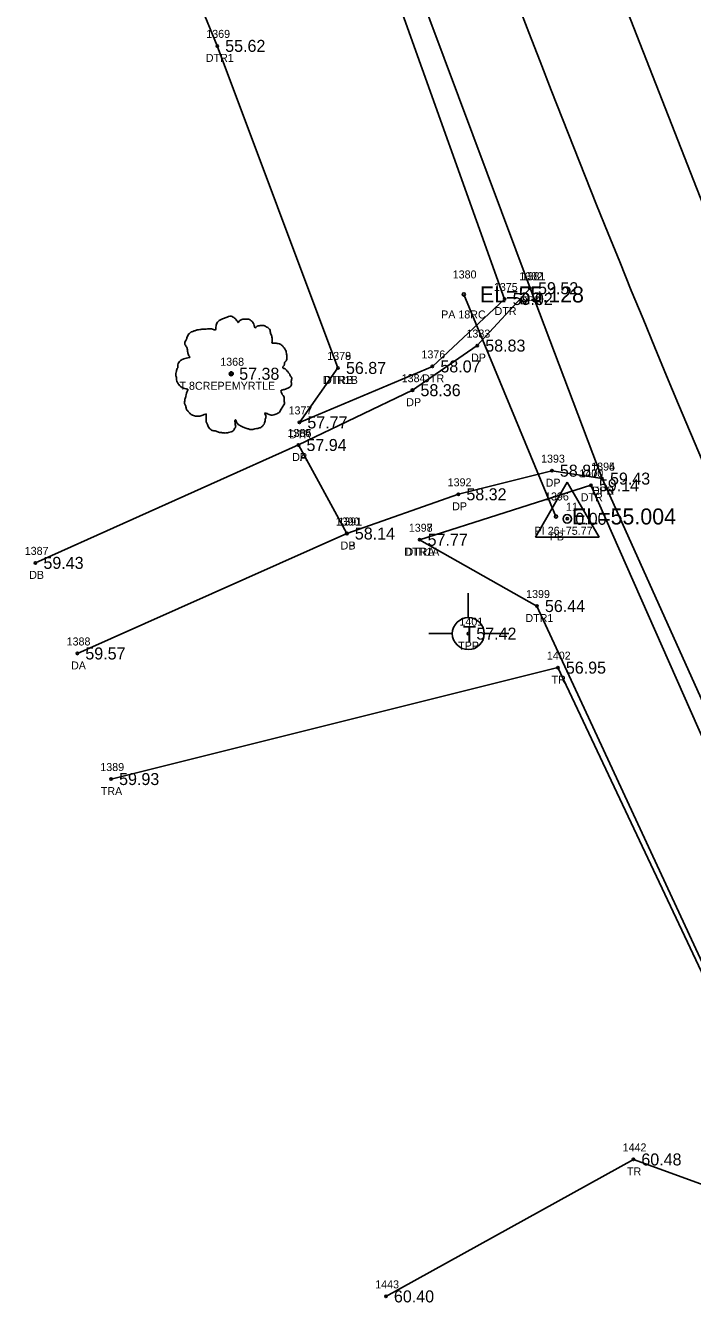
# Model space of a CAD drawing. Extents: x 2396531 to 2397633, y 770203 to 772837.
# Drawn here: x 2397059.6 to 2397143, y 771006.4 to 771166.1 of the extents above; entities that cross this region are included whole.
import ezdxf

# ---------------------------------------------------------------- set-up
doc = ezdxf.new("R2010")
doc.units = 0
for name, color, linetype in [('RD_EX_DR_Pipe', 7, 'Continuous'), ('RD_EX_DR_Pipe_txCode', 7, 'Continuous'), ('RD_EX_Driveway', 7, 'Continuous'), ('RD_EX_Driveway_txCode', 7, 'Continuous'), ('RD_EX_H2O', 7, 'Continuous'), ('RD_EX_H2O_txCode', 7, 'Continuous'), ('RD_EX_Road', 7, 'Continuous'), ('RD_EX_Road_txCode', 7, 'Continuous'), ('RD_EX_TX_Driveway_ELEV', 7, 'Continuous'), ('RD_EX_TX_H2O_ELEV', 7, 'Continuous'), ('RD_EX_TX_Road_ELEV', 7, 'Continuous'), ('RD_EX_TX_UT_ELEV', 7, 'Continuous'), ('RD_EX_TX_VEG_ELEV', 7, 'Continuous'), ('RD_EX_UT', 7, 'Continuous'), ('RD_EX_UT_txCode', 7, 'Continuous'), ('RD_EX_VEG', 7, 'Continuous'), ('RD_EX_VEG_txCode', 7, 'Continuous'), ('RD_HC_Cl', 7, 'Continuous'), ('RD_HC_Data', 7, 'Continuous'), ('RD_HC_Survey_ELEV', 7, 'Continuous'), ('RD_HC_txCode', 7, 'Continuous'), ('RD_SMD_Locator', 7, 'Continuous'), ('RD_TX_Pipe_ElevEX', 7, 'Continuous')]:
    doc.layers.add(name, color=color, linetype=linetype)

msp = doc.modelspace()

# ---------------------------------------------------------------- linework, layer by layer
at = {"layer": 'RD_EX_DR_Pipe'}
msp.add_line((2397114.38, 771132.51), (2397125.9, 771104.77), dxfattribs=at)
at = {"layer": 'RD_EX_Driveway'}
for p, q in [((2397093.7, 771113.7), (2397060.81, 771098.97)), ((2397066.05, 771087.65), (2397099.75, 771102.64))]:
    msp.add_line(p, q, dxfattribs=at)
msp.add_lwpolyline([(2397122.66, 771133.29), (2397116.06, 771126.12), (2397107.96, 771120.55), (2397093.7, 771113.7), (2397099.75, 771102.64), (2397113.7, 771107.54), (2397125.39, 771110.49), (2397131.66, 771109.5)], dxfattribs=at)
at = {"layer": 'RD_EX_H2O'}
for points in [[(2397089.23, 771210.58), (2397074.63, 771209.23), (2397066.11, 771205.28), (2397068.66, 771199.78), (2397083.54, 771163.57), (2397098.64, 771123.33)], [(2397089.23, 771210.58), (2397105.65, 771170.55), (2397119.48, 771131.94), (2397110.45, 771123.52), (2397093.81, 771116.52), (2397098.64, 771123.33)], [(2397108.85, 771101.86), (2397130.27, 771108.67), (2397157.99, 771046.03), (2397184.53, 770991.63), (2397224.53, 770918.86), (2397257.48, 770863.23)], [(2397108.85, 771101.86), (2397123.52, 771093.58), (2397147.97, 771040.86), (2397177.5, 770986.79), (2397217.86, 770915.5), (2397251.15, 770859.33)]]:
    msp.add_lwpolyline(points, dxfattribs=at)
at = {"layer": 'RD_EX_Road'}
for points in [[(2397113.76, 771228.75), (2397130.87, 771177.98), (2397154.19, 771118.49), (2397170.38, 771081.25), (2397178.53, 771063.49), (2397207.96, 771004.56), (2397238.54, 770949.11), (2397245.72, 770936.59), (2397280.76, 770876.73)], [(2397093.16, 771212.62), (2397108.35, 771171.65), (2397122.66, 771133.29), (2397131.66, 771109.5), (2397159.86, 771046.96), (2397187.02, 770992.86), (2397227.29, 770920.43), (2397260.16, 770864.73)]]:
    msp.add_lwpolyline(points, dxfattribs=at)
at = {"layer": 'RD_EX_UT'}
for p, q in [((2397114.94, 771095.2), (2397114.94, 771092.13)), ((2397110.01, 771090.15), (2397112.94, 771090.15)), ((2397116.94, 771090.15), (2397120.01, 771090.15))]:
    msp.add_line(p, q, dxfattribs=at)
msp.add_circle((2397114.94, 771090.13), 2, dxfattribs=at)
at = {"layer": 'RD_EX_VEG'}
msp.add_lwpolyline([(2397070.27, 771071.96), (2397126.14, 771085.88), (2397159.22, 771015.86), (2397135.58, 771024.43), (2397104.64, 771007.32)], dxfattribs=at)
for centre, radius in [((2397085.29, 771122.6), 0.25), ((2397085.28, 771122.58), 0.0001)]:
    msp.add_circle(centre, radius, dxfattribs=at)
for points in [[(2397085.42, 771129.77), (2397085.12, 771129.79), (2397084.8, 771129.69), (2397084.55, 771129.59), (2397084.32, 771129.52), (2397084.1, 771129.42), (2397083.8, 771129.24), (2397083.57, 771129.04), (2397083.45, 771128.79), (2397083.4, 771128.57), (2397083.35, 771128.3), (2397083.35, 771128.12), (2397083.22, 771128.1), (2397083.07, 771128.12), (2397082.82, 771128.2), (2397082.57, 771128.2), (2397082.32, 771128.2), (2397081.97, 771128.17), (2397081.63, 771128.17), (2397081.35, 771128.12), (2397081.03, 771128.07), (2397080.65, 771127.95), (2397080.3, 771127.82), (2397080, 771127.57), (2397079.75, 771127.1), (2397079.63, 771126.75), (2397079.48, 771126.5), (2397079.63, 771126.05), (2397079.8, 771125.7), (2397079.83, 771125.5), (2397079.9, 771125.07), (2397080, 771124.85), (2397080.13, 771124.65), (2397080.05, 771124.62), (2397079.68, 771124.57), (2397079.38, 771124.47), (2397078.95, 771124.25), (2397078.73, 771124.02), (2397078.63, 771123.7), (2397078.6, 771123.35), (2397078.5, 771123.15), (2397078.43, 771122.87), (2397078.4, 771122.8), (2397078.35, 771122.47), (2397078.45, 771122.02), (2397078.48, 771121.67), (2397078.6, 771121.45), (2397078.75, 771121.27), (2397078.93, 771121.02), (2397079.33, 771120.8), (2397079.65, 771120.7), (2397079.85, 771120.67), (2397079.68, 771120.17), (2397079.63, 771119.82), (2397079.5, 771119.42), (2397079.5, 771119.35), (2397079.45, 771118.87), (2397079.6, 771118.55), (2397079.68, 771118.17), (2397079.85, 771117.95), (2397080.13, 771117.65), (2397080.45, 771117.42), (2397080.95, 771117.3), (2397081.35, 771117.32), (2397081.92, 771117.5), (2397082.17, 771117.57), (2397082.15, 771117.4), (2397082.17, 771117.02), (2397082.17, 771116.6), (2397082.32, 771116.28), (2397082.42, 771116), (2397082.57, 771115.75), (2397082.9, 771115.53), (2397083.3, 771115.45), (2397083.72, 771115.3), (2397084.17, 771115.23), (2397084.67, 771115.2), (2397085.27, 771115.35), (2397085.55, 771115.48), (2397085.65, 771115.65), (2397085.85, 771116.03), (2397085.8, 771116.25), (2397085.82, 771116.85), (2397085.92, 771116.68), (2397086.1, 771116.33), (2397086.6, 771116.03), (2397087, 771115.85), (2397087.47, 771115.7), (2397087.77, 771115.63), (2397088.25, 771115.7), (2397088.62, 771115.78), (2397089, 771115.9), (2397089.3, 771116.18), (2397089.47, 771116.45), (2397089.52, 771116.73), (2397089.6, 771117.1), (2397089.65, 771117.27)], [(2397089.65, 771117.27), (2397089.57, 771117.45), (2397089.52, 771117.7), (2397089.6, 771117.67), (2397089.77, 771117.62), (2397090.05, 771117.5), (2397090.27, 771117.42), (2397090.6, 771117.45), (2397090.87, 771117.55), (2397091.32, 771117.82), (2397091.6, 771118.3), (2397091.87, 771118.7), (2397091.95, 771119.02), (2397091.9, 771119.25), (2397091.87, 771119.75), (2397091.67, 771120), (2397091.62, 771120.12), (2397091.52, 771120.52), (2397091.6, 771120.57), (2397091.87, 771120.62), (2397092.25, 771120.75), (2397092.52, 771120.87), (2397092.75, 771121.05), (2397092.82, 771121.27), (2397092.8, 771121.67), (2397092.85, 771122.07), (2397092.77, 771122.22), (2397092.67, 771122.37), (2397092.6, 771122.57), (2397092.45, 771122.72), (2397092.35, 771122.87), (2397092.25, 771122.97), (2397092.12, 771123.12), (2397091.95, 771123.25), (2397091.8, 771123.3), (2397091.75, 771123.45), (2397091.9, 771123.65), (2397091.95, 771123.75), (2397091.97, 771123.97), (2397092.2, 771124.32), (2397092.25, 771124.72), (2397092.2, 771125.15), (2397092.15, 771125.42), (2397092, 771125.7), (2397091.8, 771125.95), (2397091.67, 771126.12), (2397091.5, 771126.25), (2397091.17, 771126.37), (2397090.92, 771126.42), (2397090.57, 771126.42), (2397090.37, 771126.47), (2397090.4, 771126.52), (2397090.4, 771126.67), (2397090.4, 771126.95), (2397090.32, 771127.4), (2397090.17, 771127.9), (2397090.17, 771127.92), (2397090.07, 771128.17), (2397089.85, 771128.37), (2397089.67, 771128.47), (2397089.47, 771128.59), (2397089.22, 771128.62), (2397088.92, 771128.62), (2397088.65, 771128.57), (2397088.45, 771128.47), (2397088.27, 771128.34), (2397088.2, 771128.49), (2397088.1, 771128.79), (2397088.05, 771128.94), (2397087.9, 771129.12), (2397087.67, 771129.32), (2397087.22, 771129.44), (2397086.6, 771129.37), (2397086.3, 771129.17), (2397086.15, 771128.99), (2397086.1, 771129.12), (2397085.9, 771129.32), (2397085.8, 771129.49), (2397085.62, 771129.62), (2397085.47, 771129.72), (2397085.37, 771129.77)]]:
    msp.add_spline(points, degree=3, dxfattribs=at)
at = {"layer": 'RD_HC_Cl'}
msp.add_arc((2398682.18, 771766.08), 1671.39, 194.59125, 211.50817, dxfattribs=at)
at = {"layer": 'RD_HC_Data'}
for p, q in [((2397123.35, 771102.19), (2397127.32, 771109.07)), ((2397127.32, 771109.07), (2397131.29, 771102.19)), ((2397123.35, 771102.19), (2397131.29, 771102.19))]:
    msp.add_line(p, q, dxfattribs=at)
msp.add_circle((2397127.32, 771104.48), 0.529, dxfattribs=at)
at = {"layer": 'RD_SMD_Locator'}
for centre, radius in [((2397083.54, 771163.57), 0.15), ((2397122.66, 771133.29), 0.15), ((2397122.66, 771133.29), 0.15), ((2397114.38, 771132.51), 0.2), ((2397119.48, 771131.94), 0.15), ((2397116.06, 771126.12), 0.15), ((2397085.29, 771122.6), 0.15), ((2397098.64, 771123.33), 0.15), ((2397098.64, 771123.33), 0.15), ((2397110.45, 771123.52), 0.15), ((2397107.96, 771120.55), 0.15), ((2397093.81, 771116.52), 0.15), ((2397093.7, 771113.7), 0.15), ((2397093.7, 771113.7), 0.15), ((2397125.39, 771110.49), 0.15), ((2397131.66, 771109.5), 0.15), ((2397131.66, 771109.5), 0.15), ((2397130.27, 771108.67), 0.15), ((2397113.7, 771107.54), 0.15), ((2397125.9, 771104.77), 0.2), ((2397127.32, 771104.48), 0.15), ((2397099.75, 771102.64), 0.15), ((2397099.75, 771102.64), 0.15), ((2397108.85, 771101.86), 0.15), ((2397108.85, 771101.86), 0.15), ((2397060.81, 771098.97), 0.15), ((2397123.52, 771093.58), 0.15), ((2397114.94, 771090.13), 0.15), ((2397066.05, 771087.65), 0.15), ((2397126.14, 771085.88), 0.15), ((2397070.27, 771071.96), 0.15), ((2397135.58, 771024.43), 0.15), ((2397104.64, 771007.32), 0.15)]:
    msp.add_circle(centre, radius, dxfattribs=at)

# ---------------------------------------------------------------- texts
at = {"layer": 'RD_EX_DR_Pipe_txCode'}
for s, p in [('1380', (2397112.99, 771134.51)), ('PA 18RC', (2397111.54, 771129.51)), ('1396', (2397124.53, 771106.77)), ('PB', (2397125.12, 771101.77))]:
    msp.add_text(s, height=1, dxfattribs=at).set_placement(p)
at = {"layer": 'RD_EX_Driveway_txCode'}
for s, p in [('1382', (2397121.31, 771134.29)), ('DPA', (2397121.39, 771131.29)), ('1383', (2397114.71, 771127.12)), ('DP', (2397115.28, 771124.12)), ('1384', (2397106.61, 771121.55)), ('DP', (2397107.18, 771118.55)), ('1386', (2397092.33, 771114.7)), ('1385', (2397092.36, 771114.7)), ('DA', (2397092.91, 771111.7)), ('DP', (2397092.92, 771111.7)), ('1393', (2397124.04, 771111.49)), ('1394', (2397130.31, 771110.5)), ('1392', (2397112.36, 771108.54)), ('DP', (2397124.61, 771108.49)), ('DPB', (2397130.4, 771107.5)), ('DP', (2397112.92, 771105.54)), ('1390', (2397098.36, 771103.64)), ('1391', (2397098.68, 771103.64)), ('DB', (2397098.97, 771100.64)), ('DP', (2397098.97, 771100.64)), ('1387', (2397059.47, 771099.97)), ('DB', (2397060.03, 771096.97)), ('1388', (2397064.71, 771088.65)), ('DA', (2397065.26, 771085.65))]:
    msp.add_text(s, height=1, dxfattribs=at).set_placement(p)
at = {"layer": 'RD_EX_H2O_txCode'}
for s, p in [('1369', (2397082.17, 771164.57)), ('DTR1', (2397082.11, 771161.57)), ('1375', (2397118.14, 771132.94)), ('DTR', (2397118.22, 771129.94)), ('1376', (2397109.08, 771124.52)), ('1378', (2397097.3, 771124.33)), ('1379', (2397097.3, 771124.33)), ('DTR1B', (2397096.74, 771121.33)), ('DTRB', (2397096.9, 771121.33)), ('DTR', (2397109.18, 771121.52)), ('1377', (2397092.46, 771117.52)), ('DTR', (2397092.54, 771114.52)), ('1400', (2397128.84, 771109.67)), ('DTR', (2397129, 771106.67)), ('1397', (2397107.5, 771102.86)), ('1398', (2397107.5, 771102.86)), ('DTR1A', (2397106.93, 771099.86)), ('DTRA', (2397107.09, 771099.86)), ('1399', (2397122.17, 771094.58)), ('DTR1', (2397122.08, 771091.58))]:
    msp.add_text(s, height=1, dxfattribs=at).set_placement(p)
at = {"layer": 'RD_EX_Road_txCode'}
for s, p in [('1381', (2397121.6, 771134.29)), ('EPR', (2397121.43, 771131.29)), ('1395', (2397130.31, 771110.5)), ('EPR', (2397130.43, 771107.5))]:
    msp.add_text(s, height=1, dxfattribs=at).set_placement(p)
at = {"layer": 'RD_EX_TX_Driveway_ELEV'}
for s, p in [('59.52', (2397123.66, 771132.54)), ('58.83', (2397117.06, 771125.37)), ('58.36', (2397108.96, 771119.8)), ('57.94', (2397094.7, 771112.95)), ('57.94', (2397094.7, 771112.95)), ('58.87', (2397126.39, 771109.74)), ('59.43', (2397132.66, 771108.75)), ('58.32', (2397114.7, 771106.79)), ('58.14', (2397100.75, 771101.89)), ('58.14', (2397100.75, 771101.89)), ('59.43', (2397061.81, 771098.22)), ('59.57', (2397067.05, 771086.9))]:
    msp.add_text(s, height=1.5, dxfattribs=at).set_placement(p)
at = {"layer": 'RD_EX_TX_H2O_ELEV'}
for s, p in [('55.62', (2397084.54, 771162.82)), ('59.02', (2397120.48, 771131.19)), ('56.87', (2397099.64, 771122.58)), ('56.87', (2397099.64, 771122.58)), ('58.07', (2397111.45, 771122.77)), ('57.77', (2397094.81, 771115.77)), ('59.14', (2397131.27, 771107.92)), ('57.77', (2397109.85, 771101.11)), ('57.77', (2397109.85, 771101.11)), ('56.44', (2397124.52, 771092.83))]:
    msp.add_text(s, height=1.5, dxfattribs=at).set_placement(p)
at = {"layer": 'RD_EX_TX_Road_ELEV'}
for s, p in [('59.52', (2397123.66, 771132.54)), ('59.43', (2397132.66, 771108.75))]:
    msp.add_text(s, height=1.5, dxfattribs=at).set_placement(p)
at = {"layer": 'RD_EX_TX_UT_ELEV'}
msp.add_text('57.42', height=1.5, dxfattribs=at).set_placement((2397115.94, 771089.38))
at = {"layer": 'RD_EX_TX_VEG_ELEV'}
for s, p in [('57.38', (2397086.29, 771121.85)), ('56.95', (2397127.14, 771085.13)), ('59.93', (2397071.27, 771071.21)), ('60.48', (2397136.58, 771023.68)), ('60.40', (2397105.64, 771006.57))]:
    msp.add_text(s, height=1.5, dxfattribs=at).set_placement(p)
at = {"layer": 'RD_EX_UT'}
msp.add_text('T', height=2, dxfattribs=at).set_placement((2397114.27, 771089.08))
at = {"layer": 'RD_EX_UT_txCode'}
for s, p in [('1401', (2397113.83, 771091.13)), ('TPP', (2397113.67, 771088.13))]:
    msp.add_text(s, height=1, dxfattribs=at).set_placement(p)
at = {"layer": 'RD_EX_VEG_txCode'}
for s, p in [('1368', (2397083.92, 771123.6)), ('T 8CREPEMYRTLE', (2397078.82, 771120.6)), ('1402', (2397124.76, 771086.88)), ('TR', (2397125.35, 771083.88)), ('1389', (2397068.92, 771072.96)), ('TRA', (2397068.98, 771069.96)), ('1442', (2397134.24, 771025.43)), ('TR', (2397134.79, 771022.43)), ('1443', (2397103.3, 771008.32))]:
    msp.add_text(s, height=1, dxfattribs=at).set_placement(p)
at = {"layer": 'RD_HC_Survey_ELEV'}
msp.add_text('0.00', height=1.5, dxfattribs=at).set_placement((2397128.32, 771103.73))
at = {"layer": 'RD_HC_txCode'}
for s, p in [('11', (2397127.15, 771105.48)), ('PI 26+75.77', (2397123.23, 771102.48))]:
    msp.add_text(s, height=1, dxfattribs=at).set_placement(p)
at = {"layer": 'RD_TX_Pipe_ElevEX'}
for s, p in [('EL=55.128', (2397116.38, 771131.51)), ('EL=55.004', (2397127.9, 771103.77))]:
    msp.add_text(s, height=2, dxfattribs=at).set_placement(p)

doc.saveas('drawing.dxf')
